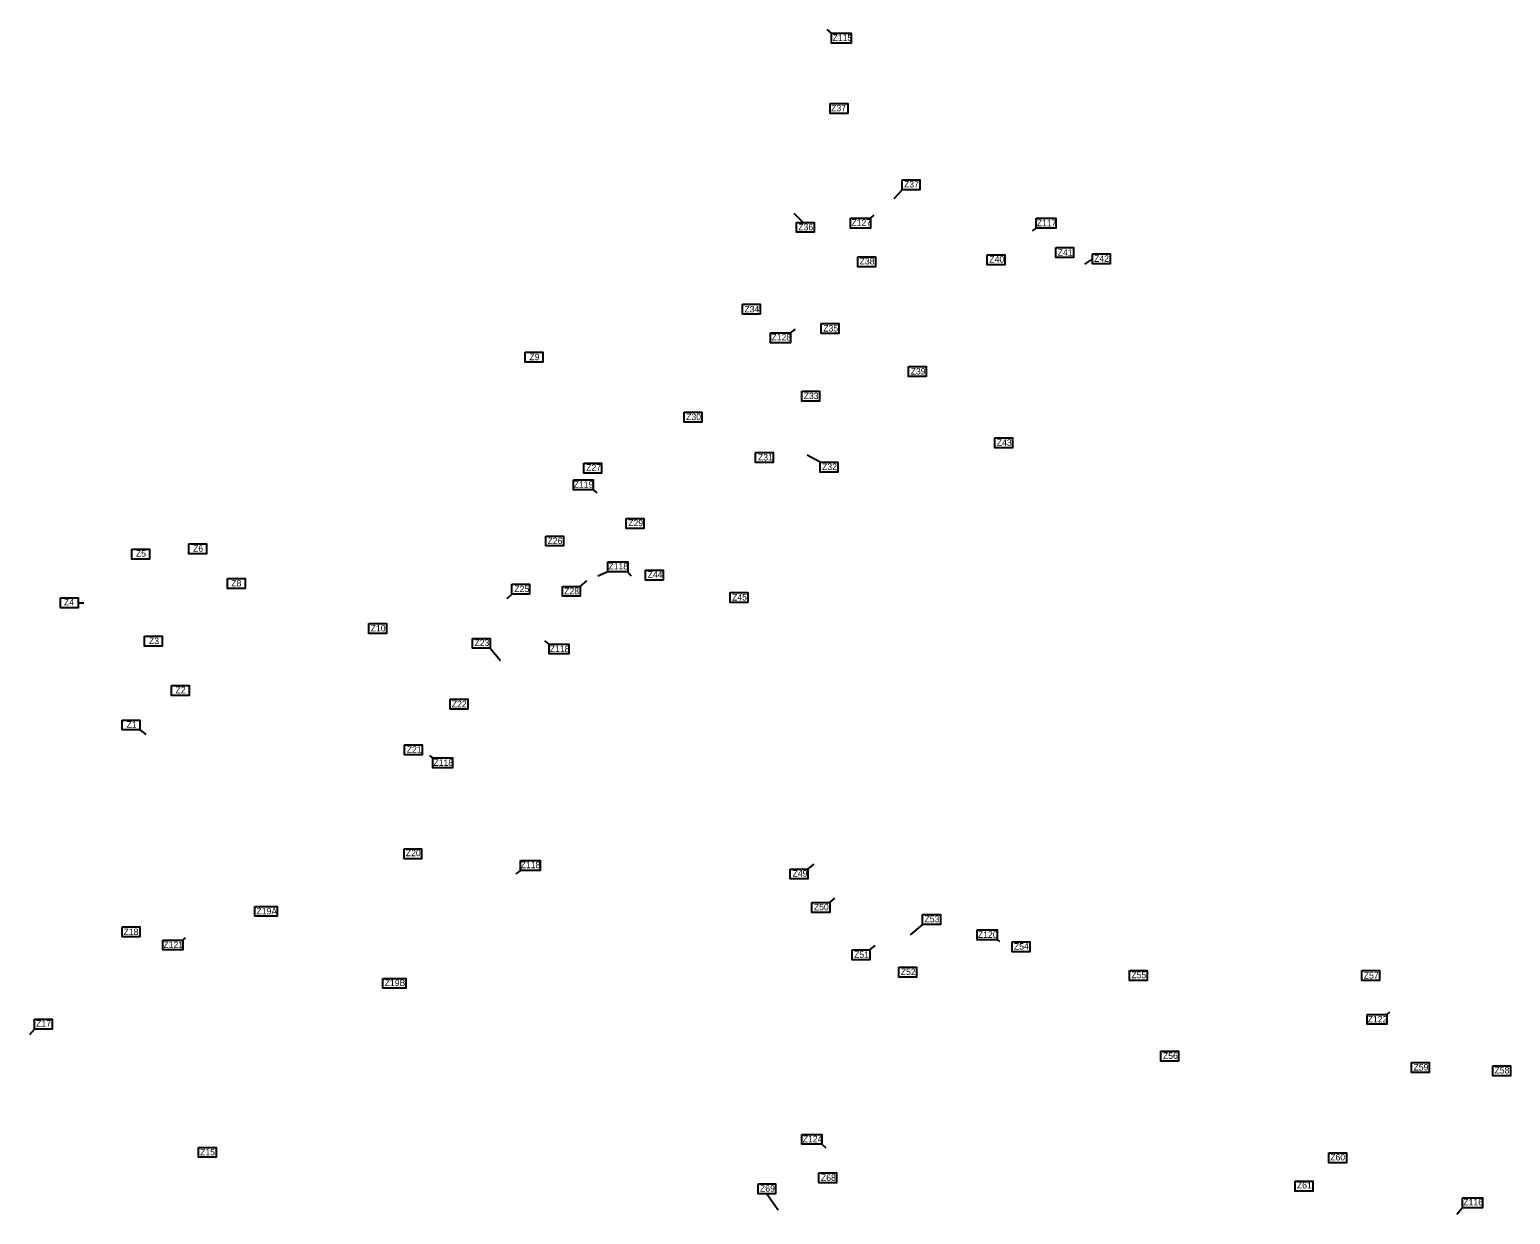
# Model space of a CAD drawing. Extents: x -443483 to -437875, y -1135204 to -1129797.
# Drawn here: x -443022 to -440729, y -1131632 to -1129797 of the extents above; entities that cross this region are included whole.
import ezdxf

# ---------------------------------------------------------------- set-up
doc = ezdxf.new("R2010")
doc.units = 0
doc.layers.add('Vrstva 3', color=7, linetype='Continuous')
doc.layers.add('Vrstva 8', color=7, linetype='Continuous')

msp = doc.modelspace()

# ---------------------------------------------------------------- linework, layer by layer
at = {"layer": 'Vrstva 3'}
for p, q in [((-441780.6, -1129802.1), (-441787.2, -1129796.7)), ((-441671, -1130044.8), (-441684, -1130058.8)), ((-441824.2, -1130095.2), (-441838, -1130081.7)), ((-441376.1, -1130151.7), (-441388.7, -1130160)), ((-441797.8, -1130466.6), (-441817.9, -1130456)), ((-442169.8, -1130659.1), (-442159.4, -1130650.4)), ((-442947.3, -1130684.5), (-442938.5, -1130684.6)), ((-442275.3, -1130671.3), (-442283.1, -1130678.3)), ((-442308.8, -1130754.9), (-442293.2, -1130773.8)), ((-442851.5, -1130881.4), (-442842.3, -1130888.4)), ((-441816.8, -1131096.9), (-441807.1, -1131089.6)), ((-441783.2, -1131148.9), (-441775.1, -1131141.9)), ((-441639.2, -1131182.7), (-441658.5, -1131198.7)), ((-441721, -1131222.3), (-441712.8, -1131215.4)), ((-443014.7, -1131344.8), (-443022.4, -1131353.5)), ((-441880.4, -1131600.1), (-441862.9, -1131625)), ((-440803, -1131621.5), (-440811.7, -1131631.9))]:
    msp.add_line(p, q, dxfattribs=at)
for points in [[(-441780.6, -1129802.1), (-441749.8, -1129802.1), (-441749.8, -1129817.5), (-441780.6, -1129817.5)], [(-441782.6, -1129911.3), (-441755.2, -1129911.3), (-441755.2, -1129926.7), (-441782.6, -1129926.7)], [(-441671, -1130029.4), (-441643.7, -1130029.4), (-441643.7, -1130044.8), (-441671, -1130044.8)], [(-441834.7, -1130095.2), (-441807.3, -1130095.2), (-441807.3, -1130110.6), (-441834.7, -1130110.6)], [(-441433.1, -1130134.4), (-441405.7, -1130134.4), (-441405.7, -1130149.8), (-441433.1, -1130149.8)], [(-441739.6, -1130148.5), (-441712.2, -1130148.5), (-441712.2, -1130163.9), (-441739.6, -1130163.9)], [(-441539.4, -1130145.7), (-441512, -1130145.7), (-441512, -1130161.1), (-441539.4, -1130161.1)], [(-441376.1, -1130144), (-441348.7, -1130144), (-441348.7, -1130159.4), (-441376.1, -1130159.4)], [(-441918.2, -1130222.1), (-441890.9, -1130222.1), (-441890.9, -1130237.5), (-441918.2, -1130237.5)], [(-441796.3, -1130252.1), (-441768.9, -1130252.1), (-441768.9, -1130267.5), (-441796.3, -1130267.5)], [(-442254.8, -1130296.3), (-442227.5, -1130296.3), (-442227.5, -1130311.7), (-442254.8, -1130311.7)], [(-441661.1, -1130318.6), (-441633.7, -1130318.6), (-441633.7, -1130334), (-441661.1, -1130334)], [(-441826.6, -1130356.8), (-441799.2, -1130356.8), (-441799.2, -1130372.2), (-441826.6, -1130372.2)], [(-442008.5, -1130389.3), (-441981.2, -1130389.3), (-441981.2, -1130404.7), (-442008.5, -1130404.7)], [(-441527.5, -1130428.9), (-441500.2, -1130428.9), (-441500.2, -1130444.3), (-441527.5, -1130444.3)], [(-441897.9, -1130451.8), (-441870.5, -1130451.8), (-441870.5, -1130467.2), (-441897.9, -1130467.2)], [(-442163.9, -1130468.1), (-442136.5, -1130468.1), (-442136.5, -1130483.5), (-442163.9, -1130483.5)], [(-441797.8, -1130466.6), (-441770.5, -1130466.6), (-441770.5, -1130482), (-441797.8, -1130482)], [(-442098.4, -1130554.1), (-442071.1, -1130554.1), (-442071.1, -1130569.5), (-442098.4, -1130569.5)], [(-442775.7, -1130593.4), (-442748.3, -1130593.4), (-442748.3, -1130608.8), (-442775.7, -1130608.8)], [(-442222.8, -1130581.2), (-442195.5, -1130581.2), (-442195.5, -1130596.5), (-442222.8, -1130596.5)], [(-442864.1, -1130601.3), (-442836.8, -1130601.3), (-442836.8, -1130616.7), (-442864.1, -1130616.7)], [(-442068.4, -1130633.9), (-442041.1, -1130633.9), (-442041.1, -1130649.3), (-442068.4, -1130649.3)], [(-442715.8, -1130647), (-442688.5, -1130647), (-442688.5, -1130662.4), (-442715.8, -1130662.4)], [(-442275.3, -1130655.9), (-442247.9, -1130655.9), (-442247.9, -1130671.3), (-442275.3, -1130671.3)], [(-442197.1, -1130659.1), (-442169.8, -1130659.1), (-442169.8, -1130674.5), (-442197.1, -1130674.5)], [(-442974.7, -1130676.8), (-442947.3, -1130676.8), (-442947.3, -1130692.2), (-442974.7, -1130692.2)], [(-441937.3, -1130668.5), (-441909.9, -1130668.5), (-441909.9, -1130683.9), (-441937.3, -1130683.9)], [(-442497.1, -1130716.5), (-442469.7, -1130716.5), (-442469.7, -1130731.9), (-442497.1, -1130731.9)], [(-442844.2, -1130736.3), (-442816.9, -1130736.3), (-442816.9, -1130751.7), (-442844.2, -1130751.7)], [(-442336.2, -1130739.6), (-442308.8, -1130739.6), (-442308.8, -1130754.9), (-442336.2, -1130754.9)], [(-442802.8, -1130812.7), (-442775.4, -1130812.7), (-442775.4, -1130828.1), (-442802.8, -1130828.1)], [(-442370.9, -1130833.9), (-442343.6, -1130833.9), (-442343.6, -1130849.2), (-442370.9, -1130849.2)], [(-442878.9, -1130866.1), (-442851.5, -1130866.1), (-442851.5, -1130881.4), (-442878.9, -1130881.4)], [(-442441.8, -1130904.7), (-442414.5, -1130904.7), (-442414.5, -1130920.1), (-442441.8, -1130920.1)], [(-442442.5, -1131065.5), (-442415.2, -1131065.5), (-442415.2, -1131080.9), (-442442.5, -1131080.9)], [(-441844.2, -1131096.9), (-441816.8, -1131096.9), (-441816.8, -1131112.3), (-441844.2, -1131112.3)], [(-442673.7, -1131154.7), (-442638.8, -1131154.7), (-442638.8, -1131170.1), (-442673.7, -1131170.1)], [(-441810.6, -1131148.9), (-441783.2, -1131148.9), (-441783.2, -1131164.3), (-441810.6, -1131164.3)], [(-442879.2, -1131186.7), (-442851.8, -1131186.7), (-442851.8, -1131202.1), (-442879.2, -1131202.1)], [(-441639.2, -1131167.3), (-441611.8, -1131167.3), (-441611.8, -1131182.7), (-441639.2, -1131182.7)], [(-441500.6, -1131209.7), (-441473.3, -1131209.7), (-441473.3, -1131225.1), (-441500.6, -1131225.1)], [(-441748.4, -1131222.3), (-441721, -1131222.3), (-441721, -1131237.7), (-441748.4, -1131237.7)], [(-441676, -1131249.1), (-441648.6, -1131249.1), (-441648.6, -1131264.5), (-441676, -1131264.5)], [(-441319, -1131254), (-441291.6, -1131254), (-441291.6, -1131269.4), (-441319, -1131269.4)], [(-440958.8, -1131254.3), (-440931.4, -1131254.3), (-440931.4, -1131269.7), (-440958.8, -1131269.7)], [(-442475.3, -1131266.3), (-442439.8, -1131266.3), (-442439.8, -1131281.7), (-442475.3, -1131281.7)], [(-443014.7, -1131329.4), (-442987.3, -1131329.4), (-442987.3, -1131344.8), (-443014.7, -1131344.8)], [(-441270.2, -1131379), (-441242.8, -1131379), (-441242.8, -1131394.4), (-441270.2, -1131394.4)], [(-440882, -1131396.5), (-440854.6, -1131396.5), (-440854.6, -1131411.9), (-440882, -1131411.9)], [(-440756.3, -1131401.9), (-440728.9, -1131401.9), (-440728.9, -1131417.3), (-440756.3, -1131417.3)], [(-442760.6, -1131528), (-442733.3, -1131528), (-442733.3, -1131543.4), (-442760.6, -1131543.4)], [(-441010.2, -1131536.4), (-440982.9, -1131536.4), (-440982.9, -1131551.8), (-441010.2, -1131551.8)], [(-441799.8, -1131567.7), (-441772.4, -1131567.7), (-441772.4, -1131583.1), (-441799.8, -1131583.1)], [(-441894.2, -1131584.7), (-441866.9, -1131584.7), (-441866.9, -1131600.1), (-441894.2, -1131600.1)], [(-441062.3, -1131580.5), (-441035, -1131580.5), (-441035, -1131595.9), (-441062.3, -1131595.9)], [(-440803, -1131606.1), (-440772.3, -1131606.1), (-440772.3, -1131621.5), (-440803, -1131621.5)]]:
    msp.add_lwpolyline(points, close=True, dxfattribs=at)
at = {"layer": 'Vrstva 8'}
for p, q in [((-441720.1, -1130088.6), (-441714.3, -1130084)), ((-441463.6, -1130104.2), (-441469.4, -1130108.5)), ((-441844, -1130266.2), (-441836.1, -1130260.9)), ((-442149.3, -1130509.6), (-442143.6, -1130514.2)), ((-442126.7, -1130636.5), (-442142.2, -1130643.1)), ((-442095.9, -1130636.5), (-442090.5, -1130642.7)), ((-442217.8, -1130748.4), (-442224.2, -1130743.6)), ((-442398, -1130924.7), (-442402.3, -1130921.1)), ((-442262.3, -1131099), (-442269.2, -1131104.3)), ((-442785.3, -1131206.9), (-442780.8, -1131203.4)), ((-441523.9, -1131206.4), (-441520.2, -1131209.2)), ((-440920.2, -1131322), (-440915.5, -1131317.9)), ((-441795.5, -1131523.2), (-441789.2, -1131529))]:
    msp.add_line(p, q, dxfattribs=at)
for points in [[(-441750.9, -1130088.6), (-441720.1, -1130088.6), (-441720.1, -1130104), (-441750.9, -1130104)], [(-441463.6, -1130088.8), (-441432.8, -1130088.8), (-441432.8, -1130104.2), (-441463.6, -1130104.2)], [(-441463.6, -1130088.8), (-441432.8, -1130088.8), (-441432.8, -1130104.2), (-441463.6, -1130104.2)], [(-441874.8, -1130266.2), (-441844, -1130266.2), (-441844, -1130281.6), (-441874.8, -1130281.6)], [(-442180.1, -1130494.2), (-442149.3, -1130494.2), (-442149.3, -1130509.6), (-442180.1, -1130509.6)], [(-442126.7, -1130621.1), (-442095.9, -1130621.1), (-442095.9, -1130636.5), (-442126.7, -1130636.5)], [(-442217.8, -1130748.4), (-442187, -1130748.4), (-442187, -1130763.8), (-442217.8, -1130763.8)], [(-442398, -1130924.7), (-442367.2, -1130924.7), (-442367.2, -1130940.1), (-442398, -1130940.1)], [(-442262.3, -1131083.6), (-442231.5, -1131083.6), (-442231.5, -1131099), (-442262.3, -1131099)], [(-442816.1, -1131206.9), (-442785.3, -1131206.9), (-442785.3, -1131222.3), (-442816.1, -1131222.3)], [(-441554.7, -1131191), (-441523.9, -1131191), (-441523.9, -1131206.4), (-441554.7, -1131206.4)], [(-440951, -1131322), (-440920.2, -1131322), (-440920.2, -1131337.4), (-440951, -1131337.4)], [(-441826.3, -1131507.9), (-441795.5, -1131507.9), (-441795.5, -1131523.2), (-441826.3, -1131523.2)]]:
    msp.add_lwpolyline(points, close=True, dxfattribs=at)

# ---------------------------------------------------------------- texts
at = {"layer": 'Vrstva 3'}
for s, p in [('Z115', (-441778.7, -1129814.2)), ('Z37', (-441780.9, -1129923.3)), ('Z37', (-441668.1, -1130041.2)), ('Z36', (-441831.8, -1130107.5)), ('Z38', (-441736.9, -1130160.4)), ('Z40', (-441536, -1130157.5)), ('Z41', (-441430, -1130146.8)), ('Z42', (-441373.7, -1130156.4)), ('Z34', (-441915.3, -1130234.7)), ('Z35', (-441793.1, -1130264.3)), ('Z9', (-442248.2, -1130308.7)), ('Z39', (-441657.8, -1130330.9)), ('Z33', (-441823.4, -1130369)), ('Z30', (-442005.5, -1130401.6)), ('Z43', (-441524.3, -1130441.2)), ('Z31', (-441894.2, -1130464.1)), ('Z27', (-442160.4, -1130480.1)), ('Z32', (-441795, -1130478.8)), ('Z29', (-442095.2, -1130565.8)), ('Z26', (-442220.1, -1130593.6)), ('Z5', (-442857.7, -1130613.2)), ('Z6', (-442769.2, -1130605.4)), ('Z44', (-442065.1, -1130645.7)), ('Z8', (-442710.1, -1130659.2)), ('Z25', (-442271.7, -1130668)), ('Z28', (-442194.4, -1130671.3)), ('Z4', (-442969.1, -1130688.5)), ('Z45', (-441934.4, -1130681)), ('Z10', (-442494.1, -1130728.9)), ('Z3', (-442837.5, -1130748.5)), ('Z23', (-442333.3, -1130751.4)), ('Z2', (-442796.3, -1130824.6)), ('Z22', (-442368.4, -1130846.3)), ('Z1', (-442872.3, -1130878.1)), ('Z21', (-442438.2, -1130916.8)), ('Z20', (-442439.7, -1131077)), ('Z49', (-441840.7, -1131108.8)), ('Z19A', (-442671, -1131167.2)), ('Z50', (-441807.7, -1131160.9)), ('Z18', (-442876.9, -1131199.2)), ('Z53', (-441636.3, -1131179.3)), ('Z54', (-441497.9, -1131221.7)), ('Z51', (-441745.4, -1131234.4)), ('Z52', (-441673.1, -1131261.1)), ('Z55', (-441315.9, -1131266)), ('Z57', (-440956, -1131266.7)), ('Z19B', (-442472.4, -1131278.3)), ('Z17', (-443012.2, -1131341)), ('Z56', (-441267.1, -1131391.1)), ('Z59', (-440878.9, -1131409)), ('Z58', (-440753.5, -1131413.6)), ('Z15', (-442758.3, -1131540.5)), ('Z60', (-441007.9, -1131548.3)), ('Z68', (-441796.7, -1131580)), ('Z69', (-441891.2, -1131596.7)), ('Z61', (-441059.6, -1131591.7)), ('Z116', (-440801.8, -1131617.8))]:
    msp.add_text(s, height=10, dxfattribs=at).set_placement(p)
at = {"layer": 'Vrstva 8'}
for s, p in [('Z127', (-441749.5, -1130100.6)), ('Z117', (-441462.5, -1130101.2)), ('Z128', (-441873.4, -1130278.2)), ('Z119', (-442179.6, -1130506.2)), ('Z118', (-442125.9, -1130632.9)), ('Z118', (-442216.7, -1130760.9)), ('Z118', (-442396.9, -1130937.1)), ('Z118', (-442261.9, -1131095.6)), ('Z121', (-442815.1, -1131219.3)), ('Z120', (-441553.6, -1131203.5)), ('Z122', (-440949.9, -1131334.5)), ('Z124', (-441824.9, -1131520.1))]:
    msp.add_text(s, height=10, dxfattribs=at).set_placement(p)

doc.saveas('drawing.dxf')
